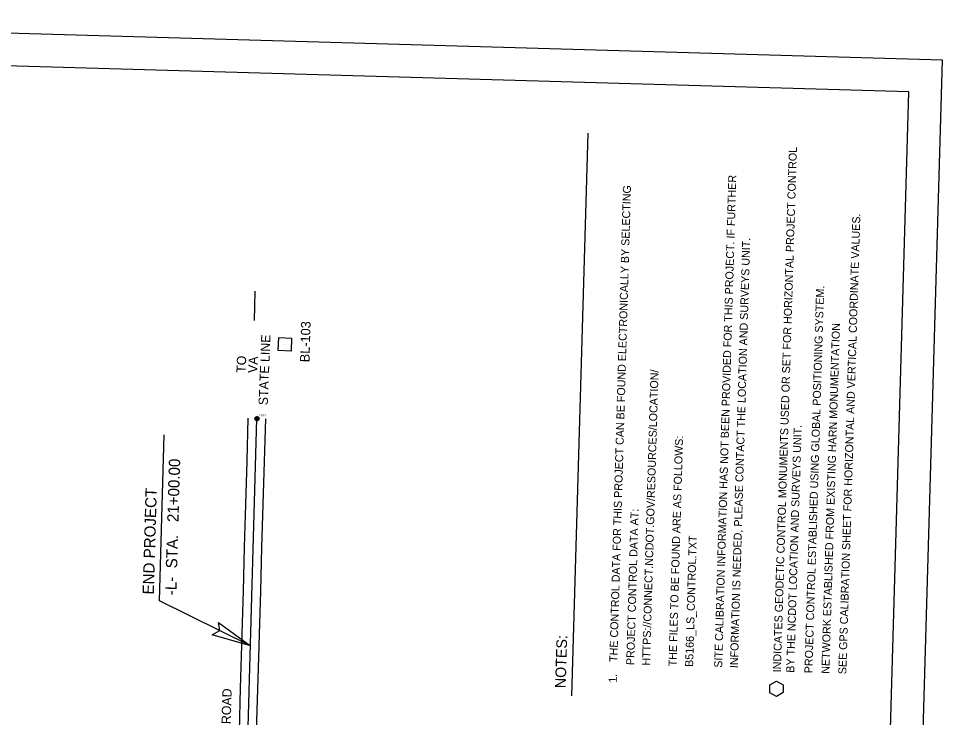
# Model space of a CAD drawing. Extents: x 2093495 to 2099559, y 984068 to 992279.
# Drawn here: x 2098496 to 2099559, y 991476 to 992279 of the extents above; entities that cross this region are included whole.
import ezdxf

# ---------------------------------------------------------------- set-up
doc = ezdxf.new("R2010")
doc.units = 0
for name, color, linetype in [('Cogo Default Point CELL', 7, 'Continuous'), ('COGO Default Point Number', 7, 'Continuous'), ('CTL GPS Vertical CELL', 7, 'Continuous'), ('CTL Sheet Border CELL', 7, 'Continuous'), ('CTL Sheet Notes CELL', 7, 'Continuous'), ('CTL Supplemental Horizontal and Vertical CELL', 7, 'Continuous'), ('Default', 7, 'Continuous'), ('Exist Roads EOP', 7, 'Continuous'), ('Exist Roads EOP Leader', 7, 'Continuous'), ('Exist Roads EOP Text', 7, 'Continuous'), ('Prop Horizontal Alignment', 7, 'Continuous'), ('Prop Horizontal Alignment Station Label', 7, 'Continuous'), ('Stewart Plot Border Xerox6279 and LJ5000', 7, 'Continuous')]:
    doc.layers.add(name, color=color, linetype=linetype)

# ---------------------------------------------------------------- blocks, each defined once
blk = doc.blocks.new('COGO DEFAULT POINT')
at = {"layer": 'Cogo Default Point CELL'}
for points in [[(-0.06, 0), (0, 0)], [(0, 0.06), (0, 0)], [(0, 0), (0.06, 0)], [(0, 0), (0, -0.06)]]:
    blk.add_lwpolyline(points, dxfattribs=at)
blk.add_circle((0, 0), 0.0469, dxfattribs=at)
blk = doc.blocks.new('CTL SUPPLEMENTAL HORIZONTAL AND VERTICAL')
at = {"layer": 'CTL Supplemental Horizontal and Vertical CELL'}
blk.add_line((0, 0), (0, 0), dxfattribs=at)
blk.add_lwpolyline([(-0.104, 0), (0.001, 0.105), (0.106, 0), (0.001, -0.105)], close=True, dxfattribs=at)
blk = doc.blocks.new('CTL GPS VERTICAL')
at = {"layer": 'CTL GPS Vertical CELL'}
blk.add_line((0, 0), (0, 0), dxfattribs=at)
blk.add_lwpolyline([(-0.0646, 0.0374), (0.0004, 0.0737), (0.0654, 0.0379), (0.0644, -0.0366), (-0.0006, -0.0743), (-0.0646, -0.0381)], close=True, dxfattribs=at)

msp = doc.modelspace()

# ---------------------------------------------------------------- linework, layer by layer
at = {"layer": 'CTL Sheet Border CELL'}
msp.add_lwpolyline([(2097934.9, 992240.5), (2097869.6, 989976.4), (2099454.5, 989930.8), (2099519.7, 992194.9)], close=True, dxfattribs=at)
at = {"layer": 'CTL Sheet Notes CELL'}
msp.add_line((2099132.4, 991500.7), (2099151, 992147.5), dxfattribs=at)
at = {"layer": 'Default'}
msp.add_lwpolyline([(2098726.1, 991584.9), (2098763.1, 991558.1), (2098718.9, 991570.9), (2098727.6, 991575.6)], close=True, dxfattribs=at)
at = {"layer": 'Exist Roads EOP'}
for points in [[(2098753.2, 991558.4), (2098753.6, 991572.4), (2098755, 991621.5), (2098756.2, 991671.6), (2098757.6, 991720.8), (2098759.1, 991770.8), (2098760.5, 991819.7)], [(2098753.2, 991558.4), (2098753.6, 991572.4), (2098755, 991621.5), (2098756.2, 991671.6), (2098757.6, 991720.8), (2098759.1, 991770.8), (2098760.5, 991819.7)], [(2098772.9, 991557.8), (2098773.4, 991571.6), (2098774.8, 991620.9), (2098776.2, 991671.3), (2098777.6, 991720.8), (2098779.1, 991769.9), (2098780.5, 991819.2)], [(2098772.9, 991557.8), (2098773.4, 991571.6), (2098774.8, 991620.9), (2098776.2, 991671.3), (2098777.6, 991720.8), (2098779.1, 991769.9), (2098780.5, 991819.2)], [(2098745.8, 991297.1), (2098746.2, 991311.1), (2098747.6, 991360.3), (2098748.8, 991410.3), (2098750.2, 991459.5), (2098751.7, 991509.5), (2098753.2, 991558.4)], [(2098765.4, 991296.5), (2098765.8, 991310.2), (2098767.2, 991359.6), (2098768.6, 991409.9), (2098770, 991459.5), (2098771.5, 991508.5), (2098772.9, 991557.8)]]:
    msp.add_lwpolyline(points, dxfattribs=at)
at = {"layer": 'Exist Roads EOP Leader'}
msp.add_lwpolyline([(2098768.1, 991965.7), (2098767.1, 991932.2)], dxfattribs=at)
at = {"layer": 'Prop Horizontal Alignment'}
msp.add_line((2098731.3, 990458.6), (2098770.5, 991819.3), dxfattribs=at)
msp.add_line((2098731.3, 990458.6), (2098770.5, 991819.3), dxfattribs=at)
at = {"layer": 'Prop Horizontal Alignment Station Label'}
for p, q in [((2098658.3, 991609.7), (2098663.8, 991800.6)), ((2098763.1, 991558.1), (2098658.3, 991609.7))]:
    msp.add_line(p, q, dxfattribs=at)
msp.add_circle((2098770.5, 991819.3), 1.5, dxfattribs=at)
at = {"layer": 'Stewart Plot Border Xerox6279 and LJ5000'}
msp.add_lwpolyline([(2099484.6, 989665.6), (2099558.5, 992231.5), (2097898.2, 992279.3), (2097824.3, 989713.4)], close=True, dxfattribs=at)

# ---------------------------------------------------------------- block references
at = {"layer": 'Cogo Default Point CELL', "xscale": 50, "yscale": 50}
msp.add_blockref('COGO DEFAULT POINT', (2098770.5, 991819.3), dxfattribs=at)
at = {"layer": 'CTL GPS Vertical CELL', "xscale": 117.97500000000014, "yscale": 117.97500000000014}
msp.add_blockref('CTL GPS VERTICAL', (2099367.6, 991508.8), dxfattribs=at)
at = {"layer": 'CTL Supplemental Horizontal and Vertical CELL', "xscale": 99.82500000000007, "yscale": 99.82500000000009, "rotation": 42.16667913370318}
msp.add_blockref('CTL SUPPLEMENTAL HORIZONTAL AND VERTICAL', (2098802.5, 991904.7), dxfattribs=at)

# ---------------------------------------------------------------- texts
at = {"layer": 'COGO Default Point Number'}
msp.add_text('L101', height=2.5, dxfattribs=at).set_placement((2098773, 991821.8))
at = {"layer": 'CTL Sheet Notes CELL'}
for s, height, rotation, p in [('INDICATES GEODETIC CONTROL MONUMENTS USED OR SET FOR HORIZONTAL PROJECT CONTROL', 9.201, 88.2443, (2099372.7, 991527.6)), ('SITE CALIBRATION INFORMATION HAS NOT BEEN PROVIDED FOR THIS PROJECT. IF FURTHER', 9.201, 88.3496, (2099305.2, 991532.9)), ('1.    THE CONTROL DATA FOR THIS PROJECT CAN BE FOUND ELECTRONICALLY BY SELECTING', 9.201, 88.3496, (2099184, 991515.6)), ('SEE GPS CALIBRATION SHEET FOR HORIZONTAL AND VERTICAL COORDINATE VALUES.', 9.201, 88.2443, (2099447.9, 991525.4)), ('INFORMATION IS NEEDED, PLEASE CONTACT THE LOCATION AND SURVEYS UNIT.', 9.201, 88.3496, (2099323.3, 991532.4)), ('PROJECT CONTROL ESTABLISHED USING GLOBAL POSITIONING SYSTEM.', 9.201, 88.2443, (2099408.9, 991526.5)), ('NETWORK ESTABLISHED FROM EXISTING HARN MONUMENTATION', 9.201, 88.2443, (2099428.4, 991525.9)), ('HTTPS://CONNECT.NCDOT.GOV/RESOURCES/LOCATION/', 9.201, 88.3496, (2099222.3, 991535.3)), ('BY THE NCDOT LOCATION AND SURVEYS UNIT.', 9.201, 88.2443, (2099388, 991527.1)), ('THE FILES TO BE FOUND ARE AS FOLLOWS:', 9.201, 88.3496, (2099252.7, 991534.5)), ('PROJECT CONTROL DATA AT:', 9.201, 88.3496, (2099204.1, 991535.9)), ('B5166_LS_CONTROL.TXT', 9.201, 88.3496, (2099271.8, 991533.9)), ('NOTES:', 12.27, 88.2443, (2099125.3, 991509.3))]:
    msp.add_text(s, height=height, rotation=rotation, dxfattribs=at).set_placement(p)
at = {"layer": 'CTL Supplemental Horizontal and Vertical CELL'}
msp.add_text('BL-103', height=10.93, rotation=88.3496, dxfattribs=at).set_placement((2098830.8, 991884))
at = {"layer": 'Exist Roads EOP Text'}
for s, height, rotation, p in [('STATE LINE', 10.62, 87.7042, (2098782.8, 991834.6)), ('TO', 10.62, 87.7042, (2098757.4, 991871.8)), ('VA', 10.62, 87.7042, (2098770.8, 991871.7)), ('CORNWALL ROAD', 10.625, 88.35, (2098737.8, 991383.6))]:
    msp.add_text(s, height=height, rotation=rotation, dxfattribs=at).set_placement(p)
at = {"layer": 'Prop Horizontal Alignment Station Label'}
for s, p in [('-L-  STA.   21+00.00', (2098677.8, 991616.2)), ('END PROJECT ', (2098651.9, 991617))]:
    msp.add_text(s, height=13, rotation=88.3496, dxfattribs=at).set_placement(p)

doc.saveas('drawing.dxf')
